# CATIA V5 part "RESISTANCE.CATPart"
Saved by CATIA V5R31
Part number: RESISTANCE
Source: Unknown
Bounding box of the stored display mesh (mm): x 0 to 3.2, y 0 to 1.6, z 0 to 0.55
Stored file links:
  \\solize.local\damia\dept\DDE_Design\10_order\2305701_JAMA_変換検証STEP3_お手本モデル作成\work\03_東洋電装_スイッチ\10_CATIA_V5\RESISTANCE.CATPart
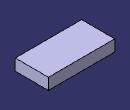
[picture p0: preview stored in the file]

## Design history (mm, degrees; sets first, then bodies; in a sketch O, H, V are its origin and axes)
WSupportSet1: ActiveGrid {3dwsupport RefPoint {point stored without definition}, 3DWOS ({wsupport Support xy-plane, RefPoint {3dwsupport}, GridIn {cartgrid Value 100, Stepbid1 0, Value 100, Stepbid2 0, Direction (1, 0, 0)}, GeometricData ({line type PtDir, Direction (1, 0, 0), Support xy-plane}; {line type PtDir, Direction (0, 1, 0), Support xy-plane})}; {wsupport Support yz-plane, RefPoint {3dwsupport}, GridIn {cartgrid Value 100, Stepbid1 0, Value 100, Stepbid2 0, Direction (0, 1, 0)}, GeometricData ({line type PtDir, Direction (0, 1, 0), Support yz-plane}; {line type PtDir, Direction (0, 0, 1), Support yz-plane})}; {wsupport Support zx-plane, RefPoint {3dwsupport}, GridIn {cartgrid Value 100, Stepbid1 0, Value 100, Stepbid2 0, Direction (0, 0, 1)}, GeometricData ({line type PtDir, Direction (0, 0, 1), Support zx-plane}; {line type PtDir, Direction (1, 0, 0), Support zx-plane})}), GeometricData ({line type PtDir, RefPoint {point stored without definition}, Direction (1, 0, 0), Support xy-plane}; {line type PtDir, RefPoint {point stored without definition}, Direction (0, 1, 0), Support xy-plane}; {line type PtDir, RefPoint {point stored without definition}, Direction (0, 1, 0), Support yz-plane}; {line type PtDir, RefPoint {point stored without definition}, Direction (0, 0, 1), Support yz-plane}; {line type PtDir, RefPoint {point stored without definition}, Direction (0, 0, 1), Support zx-plane}; {line type PtDir, RefPoint {point stored without definition}, Direction (1, 0, 0), Support zx-plane})}
Body1 (main body)
  Solid1 "PartBody": solid without history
